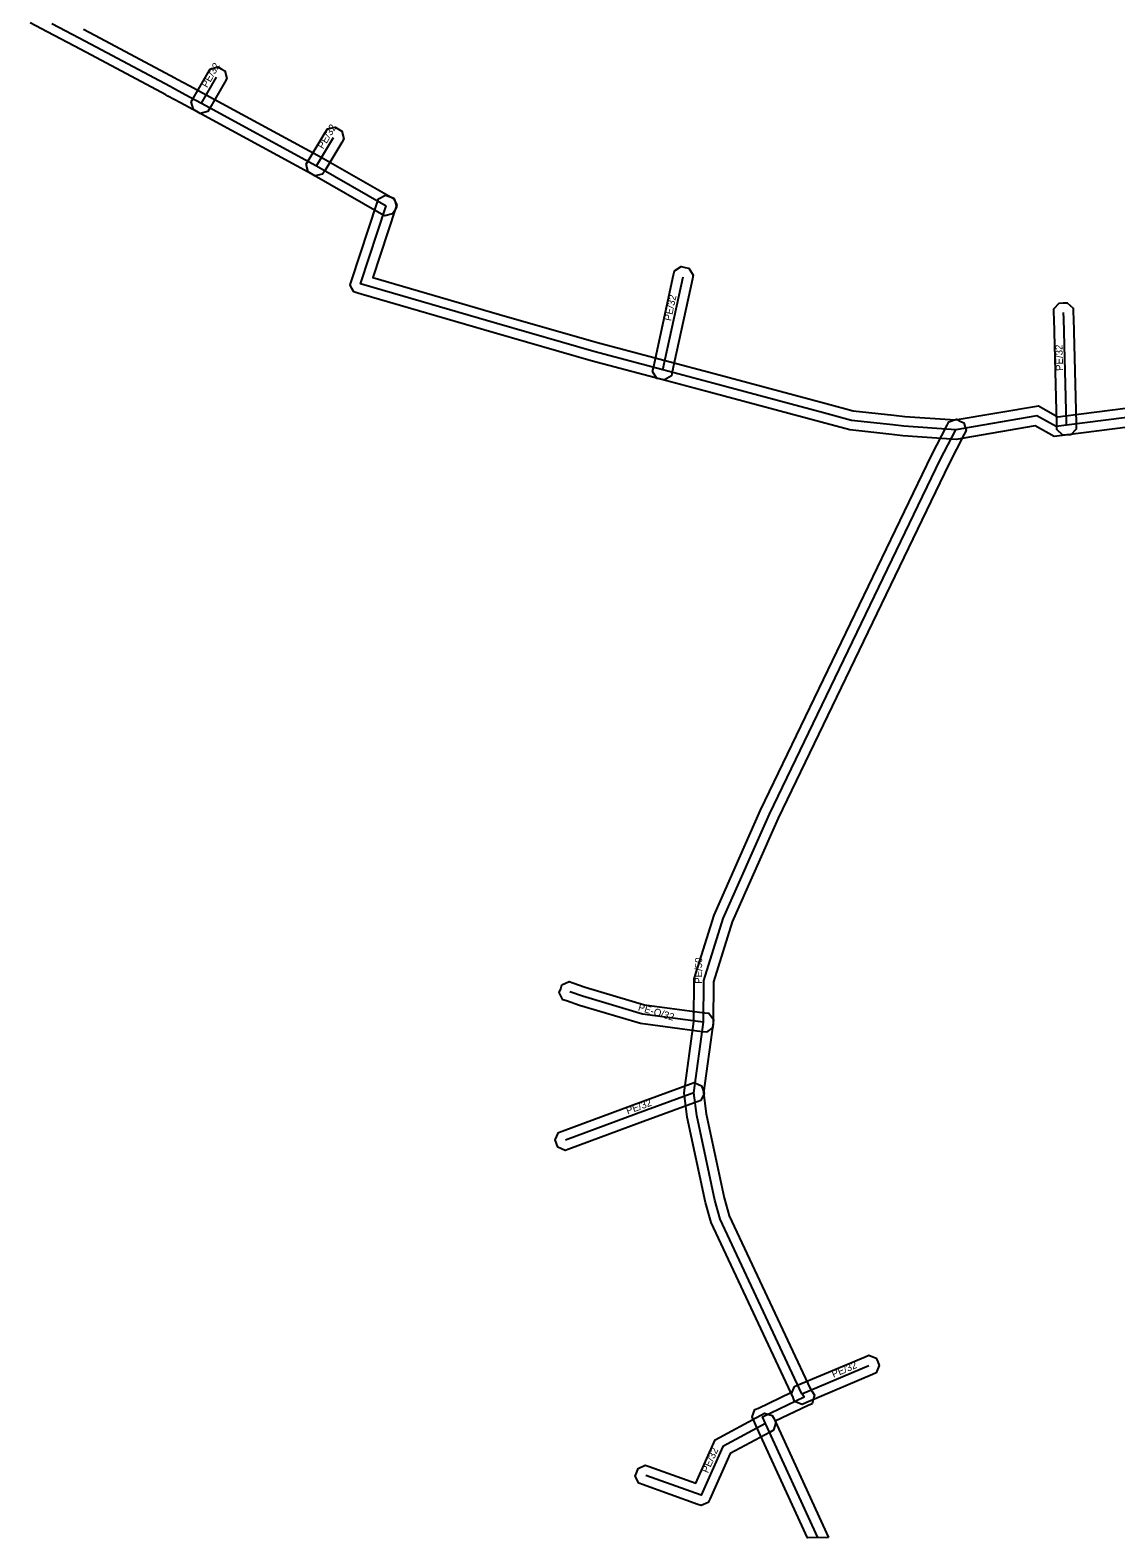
# Model space of a CAD drawing. Extents: x -682697 to -681888, y -1059966 to -1059631.
# Drawn here: x -682606.2 to -682493.5, y -1059966.2 to -1059809.7 of the extents above; entities that cross this region are included whole.
import ezdxf

# ---------------------------------------------------------------- set-up
doc = ezdxf.new("R2010")
doc.units = 0
for name, color, linetype in [('1', 7, 'Continuous'), ('24', 7, 'Continuous'), ('30', 7, 'Continuous')]:
    doc.layers.add(name, color=color, linetype=linetype)

msp = doc.modelspace()

# ---------------------------------------------------------------- linework, layer by layer
at = {"layer": '1'}
for points in [[(-682600.63, -1059809.61), (-682598.85, -1059810.55), (-682591.13, -1059814.66), (-682590.9, -1059814.79), (-682589.58, -1059815.5), (-682587.89, -1059816.42), (-682575.95, -1059822.91), (-682568.69, -1059827.06), (-682568.33, -1059827.27), (-682568.12, -1059828.07), (-682568.32, -1059828.43), (-682568.53, -1059828.79), (-682569.33, -1059829), (-682569.69, -1059828.8), (-682576.93, -1059824.65), (-682588.84, -1059818.18), (-682590.54, -1059817.26), (-682591.86, -1059816.55), (-682592.09, -1059816.42), (-682599.79, -1059812.31), (-682601.56, -1059811.38), (-682604.39, -1059809.89), (-682606.16, -1059808.94)], [(-682490.58, -1059850.71), (-682498.45, -1059851.71), (-682499.87, -1059851.89), (-682501.85, -1059850.79), (-682510.03, -1059852.19), (-682515.56, -1059851.8), (-682516.72, -1059851.66), (-682521.08, -1059851.2), (-682524.06, -1059850.4), (-682535.54, -1059847.31), (-682540.74, -1059845.93), (-682547.93, -1059844.02), (-682558, -1059841.13), (-682571.79, -1059837.1), (-682572.15, -1059837), (-682572.56, -1059836.88), (-682572.76, -1059836.51), (-682572.95, -1059836.13), (-682572.82, -1059835.73), (-682570.14, -1059827.62), (-682570.01, -1059827.22), (-682569.27, -1059826.85), (-682568.88, -1059826.98), (-682568.48, -1059827.11), (-682568.11, -1059827.85), (-682568.24, -1059828.24), (-682570.6, -1059835.37), (-682557.44, -1059839.21), (-682547.39, -1059842.1), (-682540.23, -1059843.99), (-682535.02, -1059845.37), (-682523.54, -1059848.46), (-682520.72, -1059849.22), (-682516.5, -1059849.68), (-682515.38, -1059849.8), (-682510.13, -1059850.17), (-682501.49, -1059848.71), (-682499.47, -1059849.83), (-682498.7, -1059849.73), (-682490.83, -1059848.73)]]:
    msp.add_lwpolyline(points, dxfattribs=at)
for points in [[(-682589.44, -1059817.16), (-682589.23, -1059816.8), (-682587.69, -1059814.11), (-682587.48, -1059813.75), (-682586.68, -1059813.53), (-682586.32, -1059813.74), (-682585.96, -1059813.95), (-682585.74, -1059814.75), (-682585.95, -1059815.1), (-682587.5, -1059817.8), (-682587.7, -1059818.16), (-682588.5, -1059818.37), (-682588.86, -1059818.17), (-682589.22, -1059817.96)], [(-682577.51, -1059823.62), (-682577.3, -1059823.26), (-682575.52, -1059820.32), (-682575.3, -1059819.97), (-682574.5, -1059819.77), (-682574.14, -1059819.99), (-682573.79, -1059820.2), (-682573.59, -1059821), (-682573.81, -1059821.36), (-682575.58, -1059824.3), (-682575.8, -1059824.65), (-682576.6, -1059824.85), (-682576.96, -1059824.64), (-682577.31, -1059824.42)], [(-682541.55, -1059845.15), (-682541.47, -1059844.75), (-682539.37, -1059835.1), (-682539.28, -1059834.7), (-682538.58, -1059834.25), (-682538.18, -1059834.34), (-682537.77, -1059834.43), (-682537.33, -1059835.13), (-682537.41, -1059835.53), (-682539.51, -1059845.17), (-682539.6, -1059845.58), (-682540.3, -1059846.02), (-682540.7, -1059845.94), (-682541.11, -1059845.85)], [(-682499.57, -1059851.16), (-682499.58, -1059850.75), (-682499.58, -1059850.58), (-682499.87, -1059839.68), (-682499.89, -1059839.05), (-682499.9, -1059838.64), (-682499.33, -1059838.04), (-682498.92, -1059838.02), (-682498.5, -1059838.01), (-682497.9, -1059838.58), (-682497.89, -1059839), (-682497.87, -1059839.63), (-682497.58, -1059850.53), (-682497.58, -1059850.7), (-682497.57, -1059851.11), (-682498.14, -1059851.71), (-682498.55, -1059851.72), (-682498.97, -1059851.73)], [(-682523.3, -1059966.12), (-682525.47, -1059966.17), (-682530.73, -1059954.72), (-682531.05, -1059954), (-682531.21, -1059953.63), (-682530.93, -1059952.87), (-682530.56, -1059952.7), (-682527.2, -1059951.1), (-682535.48, -1059933.46), (-682536.05, -1059931.38), (-682537.95, -1059922.52), (-682538.28, -1059920), (-682537.25, -1059912.6), (-682537.22, -1059908.17), (-682535.15, -1059901.55), (-682530.33, -1059890.66), (-682512.59, -1059853.85), (-682510.97, -1059850.72), (-682510.78, -1059850.35), (-682509.99, -1059850.1), (-682509.62, -1059850.29), (-682509.25, -1059850.48), (-682509, -1059851.27), (-682509.19, -1059851.64), (-682510.8, -1059854.75), (-682528.51, -1059891.5), (-682533.27, -1059902.25), (-682535.22, -1059908.48), (-682535.25, -1059912.74), (-682536.26, -1059920), (-682535.97, -1059922.18), (-682534.11, -1059930.9), (-682533.6, -1059932.76), (-682525.16, -1059950.75), (-682524.99, -1059951), (-682524.74, -1059951.38), (-682524.87, -1059951.82), (-682524.99, -1059952.26), (-682525.4, -1059952.45), (-682528.82, -1059954.08)], [(-682535.96, -1059913.71), (-682536.38, -1059913.66), (-682536.93, -1059913.59), (-682542.82, -1059912.81), (-682549.15, -1059910.92), (-682550.47, -1059910.46), (-682550.86, -1059910.33), (-682551.23, -1059909.58), (-682551.09, -1059909.19), (-682550.96, -1059908.8), (-682550.21, -1059908.44), (-682549.82, -1059908.57), (-682548.53, -1059909.02), (-682542.4, -1059910.85), (-682536.67, -1059911.61), (-682536.12, -1059911.68), (-682535.71, -1059911.73), (-682535.21, -1059912.39), (-682535.26, -1059912.8), (-682535.31, -1059913.21)], [(-682536.54, -1059920.8), (-682536.93, -1059920.94), (-682542.86, -1059923.11), (-682550.24, -1059925.84), (-682550.63, -1059925.98), (-682551.38, -1059925.64), (-682551.53, -1059925.25), (-682551.67, -1059924.86), (-682551.33, -1059924.11), (-682550.94, -1059923.96), (-682543.56, -1059921.23), (-682537.61, -1059919.06), (-682537.22, -1059918.92), (-682536.47, -1059919.27), (-682536.33, -1059919.66), (-682536.19, -1059920.05)], [(-682526.81, -1059950.48), (-682526.43, -1059950.31), (-682519.49, -1059947.38), (-682519.11, -1059947.22), (-682518.34, -1059947.53), (-682518.18, -1059947.91), (-682518.02, -1059948.29), (-682518.33, -1059949.06), (-682518.71, -1059949.22), (-682525.65, -1059952.16), (-682526.03, -1059952.32), (-682526.8, -1059952.01), (-682526.96, -1059951.62), (-682527.12, -1059951.24)], [(-682528.98, -1059954.99), (-682529.34, -1059955.19), (-682533.49, -1059957.43), (-682535.61, -1059962.17), (-682535.77, -1059962.52), (-682536.49, -1059962.83), (-682536.86, -1059962.7), (-682542.6, -1059960.65), (-682542.99, -1059960.51), (-682543.34, -1059959.76), (-682543.2, -1059959.37), (-682543.06, -1059958.98), (-682542.31, -1059958.63), (-682541.92, -1059958.77), (-682537.06, -1059960.51), (-682535.05, -1059955.99), (-682530.3, -1059953.43), (-682529.93, -1059953.23), (-682529.14, -1059953.47), (-682528.94, -1059953.83), (-682528.74, -1059954.2)]]:
    msp.add_lwpolyline(points, close=True, dxfattribs=at)
at = {"layer": '24'}
for points in [[(-682603.92, -1059809.01), (-682601.09, -1059810.5), (-682599.32, -1059811.43), (-682591.61, -1059815.54), (-682591.38, -1059815.67), (-682590.06, -1059816.38), (-682588.36, -1059817.3), (-682576.44, -1059823.78), (-682569.19, -1059827.93)], [(-682588.36, -1059817.3), (-682586.82, -1059814.61)], [(-682576.44, -1059823.78), (-682574.66, -1059820.84)], [(-682490.7, -1059849.72), (-682498.58, -1059850.72), (-682499.67, -1059850.86), (-682501.67, -1059849.75), (-682510.08, -1059851.18), (-682515.47, -1059850.8), (-682516.61, -1059850.67), (-682520.9, -1059850.21), (-682523.8, -1059849.43), (-682535.28, -1059846.34), (-682540.49, -1059844.96), (-682547.66, -1059843.06), (-682557.72, -1059840.17), (-682571.51, -1059836.15), (-682571.87, -1059836.04), (-682569.19, -1059827.93)], [(-682540.49, -1059844.96), (-682538.39, -1059835.32)], [(-682498.58, -1059850.72), (-682498.58, -1059850.55), (-682498.87, -1059839.66), (-682498.89, -1059839.02)], [(-682524.38, -1059966.15), (-682529.82, -1059954.31), (-682530.13, -1059953.6), (-682525.83, -1059951.55), (-682526.04, -1059951.23), (-682534.54, -1059933.11), (-682535.08, -1059931.14), (-682536.96, -1059922.35), (-682537.27, -1059920), (-682536.25, -1059912.67), (-682536.22, -1059908.32), (-682534.21, -1059901.9), (-682529.42, -1059891.07), (-682511.69, -1059854.3), (-682510.08, -1059851.18)], [(-682536.25, -1059912.67), (-682536.8, -1059912.6), (-682542.61, -1059911.83), (-682548.84, -1059909.97), (-682550.15, -1059909.52)], [(-682537.27, -1059920), (-682543.21, -1059922.17), (-682550.59, -1059924.9)], [(-682526.04, -1059951.23), (-682519.1, -1059948.3)], [(-682529.82, -1059954.31), (-682534.27, -1059956.71), (-682536.52, -1059961.76), (-682542.26, -1059959.71)]]:
    msp.add_lwpolyline(points, dxfattribs=at)

# ---------------------------------------------------------------- texts
at = {"layer": '30'}
for s, rotation, p in [('PE/32', 60.1339, (-682587.79, -1059815.75)), ('PE/32', 58.8075, (-682575.75, -1059822.11)), ('PE/32', 77.7187, (-682539.64, -1059839.94)), ('PE/32', 91.5243, (-682498.93, -1059845.07)), ('PE/50', 89.5651, (-682536.42, -1059908.68)), ('PE-O/32', 343.3767, (-682543.11, -1059911.42)), ('PE/32', 20.3004, (-682544.13, -1059922.24)), ('PE/32', 22.9259, (-682522.77, -1059949.57)), ('PE/32', 65.9849, (-682535.81, -1059959.51))]:
    msp.add_text(s, height=0.75, rotation=rotation, dxfattribs=at).set_placement(p)

doc.saveas('drawing.dxf')
